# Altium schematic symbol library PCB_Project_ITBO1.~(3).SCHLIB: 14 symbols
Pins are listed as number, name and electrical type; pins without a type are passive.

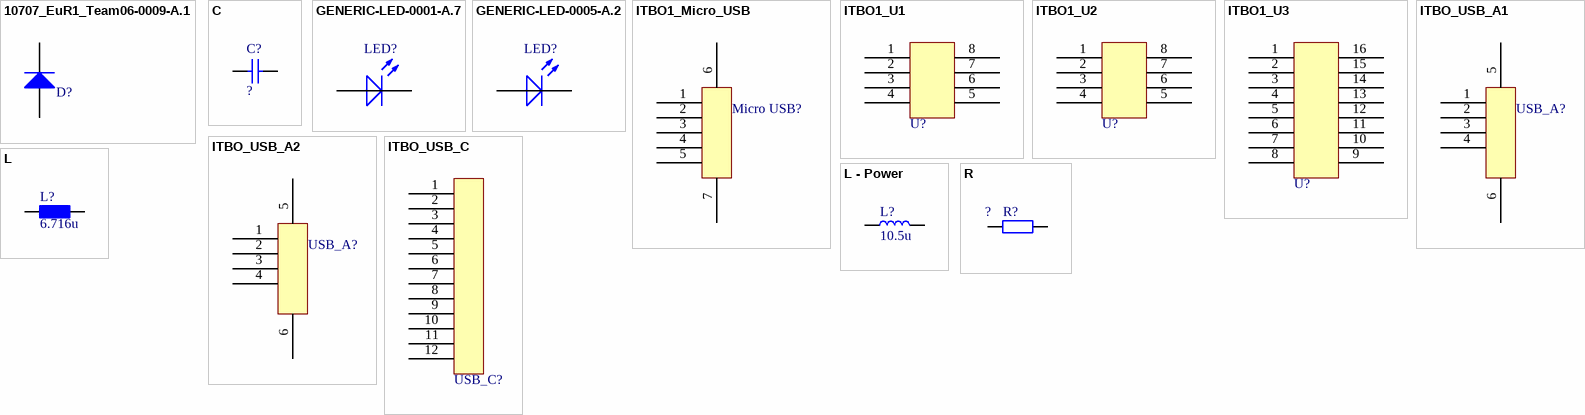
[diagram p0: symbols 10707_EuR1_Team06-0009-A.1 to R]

## 10707_EuR1_Team06-0009-A.1
designator D?, comment 1N4148W-7-F  (value not drawn)
Fast Switching Diode, 100 V, 2 A, 300 mA; Manufacturer: Diodes Incorporated
footprint DIODES_SOD123_2_H
pins: 1 K, 2 A

## C
designator C?, comment ?
Capacitor; #Manufacturer: Generic Components; #Publisher: Dr. A. Heinzelmann; #Class: Passive; Initial Voltage: 0V
simulation model CAP (Capacitor)
pins: 1, 2

## GENERIC-LED-0001-A.7
designator LED?, comment tbd  (value not drawn)
LED red; Manufacturer: generic; #ClassSub: LEDs; #Class: Generic-Components
pins: 1 K, 2 A

## GENERIC-LED-0005-A.2
designator LED?, comment tbd  (value not drawn)
LED blue; Manufacturer: generic; #ClassSub: LEDs; #Class: Generic-Components
pins: 1 K, 2 A

## ITBO1_Micro_USB
designator Micro USB?  (value not drawn)
footprint MOLEX_1051330001
pins: 1, 2, 3, 4, 5, 6, 7

## ITBO1_U1
designator U?  (value not drawn)
footprint ITBO1_U1 (TSOP, 8-Leads, Body 4.85x3.85mm, Pitch 1.27mm, IPC Medium Density)
pins: 1, 2, 3, 4, 5, 6, 7, 8

## ITBO1_U2
designator U?  (value not drawn)
footprint ITBO1_U2 (TSOP, 8-Leads, Body 4.85x3.85mm, Pitch 1.27mm, IPC Medium Density)
pins: 1, 2, 3, 4, 5, 6, 7, 8

## ITBO1_U3
designator U?  (value not drawn)
footprint ITBO1_U3
pins: 1, 2, 3, 4, 5, 6, 7, 8, 9, 10, 11, 12, 13, 14, 15, 16

## ITBO_USB_A1
designator USB_A?  (value not drawn)
pins: 1, 2, 3, 4, 5, 6

## ITBO_USB_A2
designator USB_A?  (value not drawn)
footprint MOLEX_48037-0001
pins: 1, 2, 3, 4, 5, 6

## ITBO_USB_C
designator USB_C?  (value not drawn)
pins: 1, 2, 3, 4, 5, 6, 7, 8, 9, 10, 11, 12

## L
designator L?  value 6.716u  (hidden comment: L)
Inductor; #Manufacturer: Generic Components; #Publisher: Dr. A. Heinzelmann; #Class: Passive; #ClassSub: Resistor
simulation model Inductor (ideal Inductor)
pins: 1, 2

## L - Power
designator L?, comment 10.5u
Inductor - Power; #Manufacturer: Generic Components; #Publisher: Dr. A. Heinzelmann; #Class: Passive; #ClassSub: Resistor
simulation model Inductor (ideal Inductor)
footprint WE-TPC (Power-Choke WE-TPC 2.8 x 2.8)
pins: 1, 2

## R
designator R?, comment ?
Resistor; #Manufacturer: Generic Components; #Publisher: Dr. A. Heinzelmann; #Class: Passive
simulation model RESISTOR (Resistor (Standard))
pins: 1, 2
